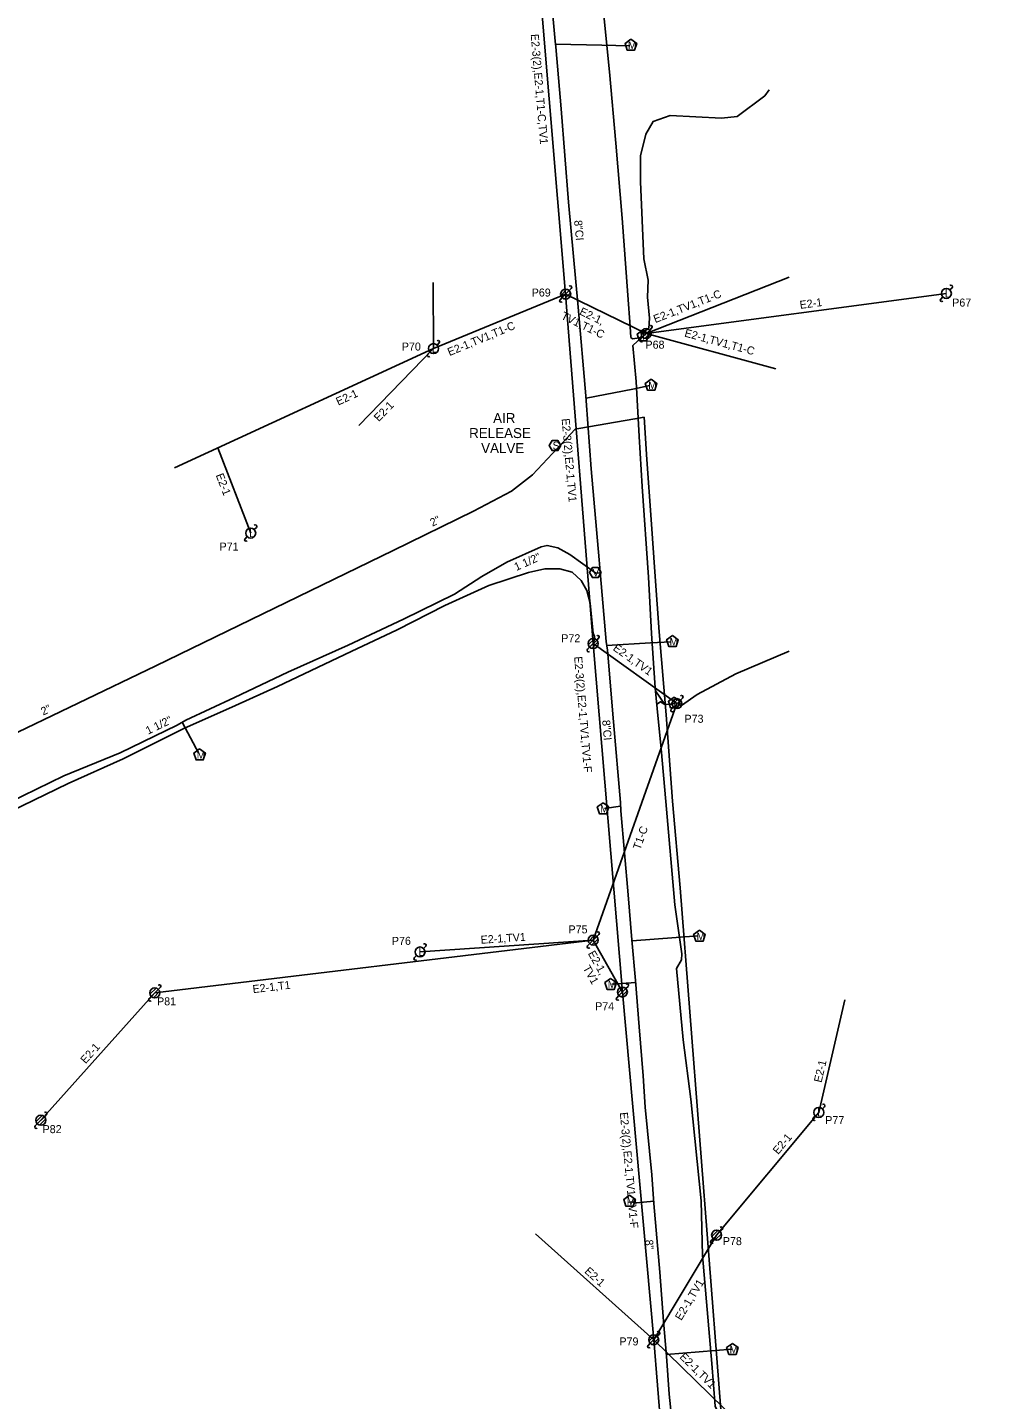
# Model space of a CAD drawing. Extents: x 1614474 to 1865144, y 1098877 to 1212550.
# Drawn here: x 1755985 to 1756469, y 1168201 to 1168887 of the extents above; entities that cross this region are included whole.
import ezdxf

# ---------------------------------------------------------------- set-up
doc = ezdxf.new("R2010")
doc.units = 0
for name, color, linetype in [('RD_EX_SU_Elec', 7, 'Continuous'), ('RD_EX_SU_H2O', 7, 'Continuous'), ('RD_EX_SU_Ovhd', 7, 'Continuous'), ('RD_EX_SU_Pole', 7, 'Continuous'), ('RD_EX_SU_Sewer', 7, 'Continuous'), ('RD_EX_SU_Telecom', 7, 'Continuous'), ('RD_EX_SU_TX_H2O', 7, 'Continuous'), ('RD_EX_SU_TX_Pole', 7, 'Continuous'), ('RD_EX_SU_TX_Sewer', 7, 'Continuous')]:
    doc.layers.add(name, color=color, linetype=linetype)

# ---------------------------------------------------------------- blocks, each defined once
blk = doc.blocks.new('SUE_PP')
at = {"layer": 'RD_EX_SU_Pole'}
for p, q in [((-2.41, -0.65), (0.65, 2.41)), ((-1.77, -1.77), (1.77, 1.77)), ((-0.65, -2.41), (2.41, 0.65)), ((1.77, 1.77), (2.83, 2.83)), ((-2.83, -2.83), (-1.77, -1.77))]:
    blk.add_line(p, q, dxfattribs=at)
blk.add_circle((0, 0), 2.5, dxfattribs=at)
for centre, start, end in [((2.3, 3.36), 315, 135), ((-2.3, -3.36), 135, 315)]:
    blk.add_arc(centre, 0.75, start, end, dxfattribs=at)
blk = doc.blocks.new('SUE_WM')
at = {"layer": 'RD_EX_SU_H2O'}
blk.add_lwpolyline([(0, 3.05), (-2.9, 0.94), (-1.79, -2.47), (1.79, -2.47), (2.9, 0.94)], close=True, dxfattribs=at)
blk.add_text('M', height=3.75, dxfattribs=at).set_placement((-1.43, -1.88))

msp = doc.modelspace()

# ---------------------------------------------------------------- linework, layer by layer
at = {"layer": 'RD_EX_SU_Elec'}
msp.add_lwpolyline([(1756310.9, 1168548.03), (1756311.85, 1168547.94), (1756319.53, 1168553.43), (1756338.93, 1168563.75), (1756365.66, 1168575.17)], dxfattribs=at)
at = {"layer": 'RD_EX_SU_H2O'}
for p, q in [((1756062.25, 1168539.6), (1756070.5, 1168524)), ((1756273.26, 1168496.58), (1756281.34, 1168497.65)), ((1756287.04, 1168430.3), (1756320.14, 1168432.8)), ((1756288.92, 1168409.56), (1756276.99, 1168408.7)), ((1756304.2, 1168223.57), (1756336.98, 1168226.24))]:
    msp.add_line(p, q, dxfattribs=at)
for points in [[(1756215.37, 1169057.62), (1756230.39, 1169005.87), (1756236.54, 1168978.79), (1756239.26, 1168962.91), (1756241.89, 1168945.6), (1756243.12, 1168936.58), (1756246.24, 1168905.88), (1756248.65, 1168879.97), (1756248.92, 1168877.19), (1756251.65, 1168846.26), (1756255.24, 1168799.63), (1756260.07, 1168747.12), (1756263.99, 1168702.78), (1756264.18, 1168700.31), (1756266.66, 1168666.35), (1756270.56, 1168620.84), (1756271.23, 1168612.87), (1756274.2, 1168580.03), (1756274.73, 1168575.57), (1756277.71, 1168539.82), (1756281.24, 1168499.51), (1756281.45, 1168495.4), (1756285.17, 1168453.36)], [(1756248.78, 1168878.57), (1756272.01, 1168878.03), (1756285.94, 1168877.77)], [(1756264.08, 1168701.54), (1756287.44, 1168706.15), (1756295.88, 1168707.93)], [(1755975.7, 1168499.57), (1756003.04, 1168512.76), (1756031.13, 1168524.34), (1756059.76, 1168538.21), (1756064.06, 1168540.6), (1756088.33, 1168551.96), (1756115.01, 1168564.64), (1756145.13, 1168578.2), (1756172.77, 1168591.2), (1756198.31, 1168603.56), (1756212.03, 1168612.5), (1756224.54, 1168619.67), (1756241.62, 1168627.3), (1756244.58, 1168627.99), (1756249.94, 1168626.83), (1756255.98, 1168623.41), (1756268.92, 1168614.21), (1756271.1, 1168614.34)], [(1756274.45, 1168577.9), (1756296.33, 1168579.27), (1756306.66, 1168579.86)], [(1756285.17, 1168453.36), (1756286.98, 1168430.89), (1756288.84, 1168410.54), (1756290.69, 1168387.38), (1756292.59, 1168362.89), (1756293.61, 1168347.16), (1756296.92, 1168313.47), (1756298.02, 1168299), (1756300.93, 1168264.73), (1756302.72, 1168240.2), (1756304.28, 1168222.7), (1756305.65, 1168203.75), (1756307.59, 1168184.55), (1756309.19, 1168163.34), (1756313.11, 1168117.87), (1756314.27, 1168105.58), (1756316.49, 1168082.9), (1756317.85, 1168067.08)], [(1756297.93, 1168300.23), (1756289.24, 1168299.38), (1756286.37, 1168299.96)]]:
    msp.add_lwpolyline(points, dxfattribs=at)
for points in [[(1756286.47, 1168881.05), (1756283.57, 1168878.94), (1756284.68, 1168875.53), (1756288.26, 1168875.53), (1756289.37, 1168878.94)], [(1756296.58, 1168711.11), (1756293.68, 1168709), (1756294.79, 1168705.59), (1756298.37, 1168705.59), (1756299.48, 1168709)], [(1756271.59, 1168614.42), (1756270.14, 1168616.92), (1756267.26, 1168616.92), (1756265.81, 1168614.42), (1756267.26, 1168611.92), (1756270.14, 1168611.92)], [(1756307.26, 1168582.93), (1756304.36, 1168580.82), (1756305.47, 1168577.41), (1756309.06, 1168577.41), (1756310.16, 1168580.82)], [(1756070.92, 1168526.31), (1756068.02, 1168524.2), (1756069.13, 1168520.79), (1756072.71, 1168520.79), (1756073.82, 1168524.2)], [(1756272.55, 1168499.41), (1756269.65, 1168497.3), (1756270.76, 1168493.89), (1756274.34, 1168493.89), (1756275.45, 1168497.3)]]:
    msp.add_lwpolyline(points, close=True, dxfattribs=at)
at = {"layer": 'RD_EX_SU_Ovhd'}
for p, q in [((1756241.59, 1168899.03), (1756253.88, 1168753.63)), ((1756294.1, 1168733.88), (1756365.67, 1168762.04)), ((1756187.81, 1168726.37), (1756187.57, 1168759.45)), ((1756294.1, 1168733.88), (1756444.18, 1168753.95)), ((1756187.81, 1168726.37), (1756253.88, 1168753.63)), ((1756253.88, 1168753.63), (1756294.1, 1168733.88)), ((1756253.88, 1168753.63), (1756267.62, 1168578.94)), ((1756294.1, 1168733.88), (1756358.94, 1168716.31)), ((1756058.29, 1168666.79), (1756187.81, 1168726.37)), ((1756150.48, 1168687.93), (1756187.81, 1168726.37)), ((1756080.07, 1168676.81), (1756096.45, 1168634.17)), ((1756267.62, 1168578.94), (1756309.52, 1168548.91)), ((1756267.62, 1168578.94), (1756282.23, 1168404.77)), ((1756267.68, 1168430.74), (1756309.52, 1168548.91)), ((1756048.5, 1168404.33), (1756267.68, 1168430.74)), ((1756181.09, 1168424.8), (1756267.68, 1168430.74)), ((1756267.68, 1168430.74), (1756282.23, 1168404.77)), ((1755991.54, 1168340.68), (1756048.5, 1168404.33)), ((1756282.23, 1168404.77), (1756297.87, 1168230.98)), ((1756380.41, 1168344.61), (1756393.49, 1168400.89)), ((1756329.33, 1168283.25), (1756380.41, 1168344.61)), ((1756238.72, 1168284), (1756297.87, 1168230.98)), ((1756297.87, 1168230.98), (1756329.33, 1168283.25)), ((1756297.87, 1168230.98), (1756339.88, 1168189.94)), ((1756297.87, 1168230.98), (1756312.84, 1168052.28))]:
    msp.add_line(p, q, dxfattribs=at)
at = {"layer": 'RD_EX_SU_Pole'}
for p, q in [((1756445.95, 1168755.71), (1756447.01, 1168756.78)), ((1756441.35, 1168751.12), (1756442.41, 1168752.18)), ((1756291.68, 1168733.24), (1756294.75, 1168736.3)), ((1756292.33, 1168732.12), (1756295.87, 1168735.65)), ((1756293.45, 1168731.47), (1756296.51, 1168734.53)), ((1756295.87, 1168735.65), (1756296.93, 1168736.71)), ((1756189.58, 1168728.14), (1756190.64, 1168729.2)), ((1756291.27, 1168731.05), (1756292.33, 1168732.12)), ((1756184.99, 1168723.54), (1756186.05, 1168724.6)), ((1756093.62, 1168631.34), (1756094.68, 1168632.4)), ((1756098.22, 1168635.93), (1756099.28, 1168636.99)), ((1756264.79, 1168576.11), (1756265.85, 1168577.17)), ((1756265.21, 1168578.29), (1756268.27, 1168581.35)), ((1756265.85, 1168577.17), (1756269.39, 1168580.71)), ((1756266.97, 1168576.52), (1756270.04, 1168579.59)), ((1756269.39, 1168580.71), (1756270.45, 1168581.77)), ((1756307.1, 1168548.26), (1756310.17, 1168551.32)), ((1756307.75, 1168547.14), (1756311.29, 1168550.67)), ((1756308.87, 1168546.49), (1756311.93, 1168549.55)), ((1756311.29, 1168550.67), (1756312.35, 1168551.73)), ((1756306.69, 1168546.08), (1756307.75, 1168547.14)), ((1756182.85, 1168426.57), (1756183.92, 1168427.63)), ((1756178.26, 1168421.98), (1756179.32, 1168423.04)), ((1756046.08, 1168403.69), (1756049.15, 1168406.75)), ((1756046.73, 1168402.57), (1756050.27, 1168406.1)), ((1756047.85, 1168401.92), (1756050.91, 1168404.98)), ((1756050.27, 1168406.1), (1756051.33, 1168407.16)), ((1756045.67, 1168401.51), (1756046.73, 1168402.57)), ((1755989.13, 1168340.03), (1755992.19, 1168343.1)), ((1755993.31, 1168342.45), (1755994.37, 1168343.51)), ((1756377.58, 1168341.79), (1756378.65, 1168342.85)), ((1756382.18, 1168346.38), (1756383.24, 1168347.44)), ((1755988.72, 1168337.85), (1755989.78, 1168338.91)), ((1755989.78, 1168338.91), (1755993.31, 1168342.45)), ((1755990.9, 1168338.27), (1755993.96, 1168341.33))]:
    msp.add_line(p, q, dxfattribs=at)
for centre in [(1756444.18, 1168753.95), (1756294.1, 1168733.88), (1756187.81, 1168726.37), (1756096.45, 1168634.17), (1756267.62, 1168578.94), (1756309.52, 1168548.91), (1756181.09, 1168424.8), (1756048.5, 1168404.33), (1755991.54, 1168340.68), (1756380.41, 1168344.61)]:
    msp.add_circle(centre, 2.5, dxfattribs=at)
for centre, start, end in [((1756446.48, 1168757.31), 315, 135), ((1756441.88, 1168750.59), 135, 315), ((1756296.4, 1168737.24), 315, 135), ((1756190.11, 1168729.73), 315, 135), ((1756291.8, 1168730.52), 135, 315), ((1756185.52, 1168723.01), 135, 315), ((1756098.75, 1168637.52), 315, 135), ((1756094.15, 1168630.81), 135, 315), ((1756269.92, 1168582.3), 315, 135), ((1756265.32, 1168575.58), 135, 315), ((1756311.82, 1168552.26), 315, 135), ((1756307.22, 1168545.55), 135, 315), ((1756183.39, 1168428.16), 315, 135), ((1756178.79, 1168421.45), 135, 315), ((1756050.8, 1168407.69), 315, 135), ((1756046.2, 1168400.98), 135, 315), ((1755993.84, 1168344.04), 315, 135), ((1756382.71, 1168347.97), 315, 135), ((1755989.25, 1168337.32), 135, 315), ((1756378.11, 1168341.26), 135, 315)]:
    msp.add_arc(centre, 0.75, start, end, dxfattribs=at)
at = {"layer": 'RD_EX_SU_Sewer'}
for points in [[(1755833.4, 1168520.19), (1755854.68, 1168510.84), (1755875.52, 1168502.34), (1755895.06, 1168493.1), (1755930.11, 1168510.09), (1755971.34, 1168530.46), (1756049.09, 1168567.75), (1756167.6, 1168625.42), (1756207.81, 1168645.15), (1756226.79, 1168655.14), (1756237.27, 1168663.29), (1756249.83, 1168676.69), (1756258.66, 1168686.07), (1756260.41, 1168686.42), (1756288.47, 1168691.24), (1756293.05, 1168692.1), (1756294.39, 1168670.91), (1756296.55, 1168641.01), (1756298.7, 1168612.4), (1756300.63, 1168584.8), (1756304.07, 1168543.33), (1756307.31, 1168500.11), (1756311.13, 1168456.78)], [(1756311.13, 1168456.78), (1756340.11, 1168085.05), (1756468.76, 1168092.7)]]:
    msp.add_lwpolyline(points, dxfattribs=at)
msp.add_lwpolyline([(1756251.47, 1168677.88), (1756250.02, 1168680.38), (1756247.13, 1168680.38), (1756245.69, 1168677.88), (1756247.13, 1168675.38), (1756250.02, 1168675.38)], close=True, dxfattribs=at)
at = {"layer": 'RD_EX_SU_Telecom'}
for p, q in [((1756293.19, 1168733.16), (1756293.87, 1168733.5)), ((1756298.77, 1168555.29), (1756303.45, 1168548.55)), ((1756303.45, 1168548.55), (1756307.13, 1168548.81)), ((1756308.14, 1168548.73), (1756308.41, 1168548.95))]:
    msp.add_line(p, q, dxfattribs=at)
for points in [[(1756174.94, 1169278.95), (1756160.29, 1169274.63), (1756159.03, 1169273.37), (1756165.27, 1169254.63), (1756173.7, 1169231.35), (1756183.01, 1169207.77), (1756193.5, 1169184.2), (1756200.36, 1169172.13), (1756213.48, 1169138.98), (1756222.54, 1169112.66), (1756230.85, 1169093.5), (1756238.34, 1169069.67), (1756245.15, 1169047.16), (1756251.74, 1169025.59), (1756258.67, 1168998.39), (1756265.3, 1168962.17), (1756268.66, 1168936.68), (1756271.99, 1168905.49), (1756273.23, 1168889.45), (1756275.78, 1168864.66), (1756278.96, 1168829.09), (1756282.05, 1168791.5), (1756284.91, 1168753.06), (1756286.16, 1168737.41)], [(1756292.67, 1168733.31), (1756293.39, 1168735.3), (1756295.52, 1168736.44), (1756295.74, 1168741.6), (1756294.85, 1168752.15), (1756295.1, 1168760.59), (1756292.91, 1168771.17), (1756291.26, 1168809.66), (1756291.35, 1168822.77), (1756293.92, 1168833.48), (1756297.58, 1168839.9), (1756306.15, 1168842.88), (1756331.85, 1168841.48), (1756339.56, 1168842.45), (1756353.44, 1168852.75), (1756355.66, 1168855.7)], [(1756286.16, 1168737.41), (1756286.44, 1168731.95), (1756287.27, 1168731.22), (1756290.84, 1168731.69), (1756292.18, 1168732.6)], [(1756292.28, 1168732.37), (1756287.5, 1168727.91), (1756289.04, 1168709.92), (1756290.67, 1168682.41), (1756292.1, 1168657.37), (1756295.3, 1168612.12), (1756296.82, 1168584.05), (1756298.63, 1168556.78), (1756299.56, 1168546.57), (1756301.65, 1168526.28), (1756303.91, 1168500.06), (1756308.42, 1168448.32)], [(1755964.85, 1168489.47), (1756005.15, 1168509.07), (1756032.74, 1168521.32), (1756062.96, 1168536.44), (1756088.88, 1168547.91), (1756109.77, 1168557.41), (1756146.73, 1168574.9), (1756169.62, 1168585.89), (1756193.45, 1168598.04), (1756215.54, 1168607.94), (1756235.28, 1168614.53), (1756243.52, 1168616.32), (1756250.98, 1168616.31), (1756257.16, 1168614.56), (1756261.69, 1168610.41), (1756264.47, 1168605.48), (1756266.13, 1168599.1), (1756267.65, 1168584.1), (1756268.31, 1168582.49), (1756268.17, 1168580.06)], [(1756307.4, 1168548.66), (1756303.49, 1168548.53), (1756301.24, 1168549.84), (1756299.37, 1168548.62)], [(1756308.42, 1168448.32), (1756311.91, 1168423.81), (1756311.76, 1168420.79), (1756309.33, 1168416.48), (1756312.58, 1168380.89), (1756316.49, 1168351.19), (1756321.57, 1168300.36), (1756322.32, 1168273.16), (1756326.95, 1168219.13), (1756328.55, 1168197.8), (1756329.78, 1168195.34), (1756338.22, 1168190.16)]]:
    msp.add_lwpolyline(points, dxfattribs=at)
for points in [[(1756292.52, 1168735.74), (1756289.66, 1168733.67), (1756290.75, 1168730.31), (1756294.28, 1168730.31), (1756295.37, 1168733.67)], [(1756308.09, 1168552.21), (1756305.23, 1168550.14), (1756306.32, 1168546.79), (1756309.85, 1168546.79), (1756310.94, 1168550.14)]]:
    msp.add_lwpolyline(points, close=True, dxfattribs=at)

# ---------------------------------------------------------------- block references
at = {"layer": 'RD_EX_SU_H2O'}
for p in [(1756320.75, 1168432.64), (1756276.37, 1168408.55), (1756285.82, 1168300.15), (1756337.24, 1168226.1)]:
    msp.add_blockref('SUE_WM', p, dxfattribs=at)
at = {"layer": 'RD_EX_SU_Pole'}
for p in [(1756253.88, 1168753.63), (1756267.68, 1168430.74), (1756282.23, 1168404.77), (1756329.33, 1168283.25), (1756297.87, 1168230.98)]:
    msp.add_blockref('SUE_PP', p, dxfattribs=at)

# ---------------------------------------------------------------- texts
at = {"layer": 'RD_EX_SU_H2O'}
for s, p in [('M', (1756285.04, 1168876.12)), ('M', (1756295.15, 1168706.18)), ('V', (1756267.27, 1168612.54)), ('M', (1756305.83, 1168578)), ('M', (1756069.49, 1168521.38)), ('M', (1756271.12, 1168494.48))]:
    msp.add_text(s, height=3.75, dxfattribs=at).set_placement(p)
at = {"layer": 'RD_EX_SU_Ovhd'}
for s, rotation, p in [('E2-3(2),E2-1,T1-C,TV1', 274.8814, (1756236.41, 1168883.46)), ('E2-1,TV1,T1-C', 21.4774, (1756298.69, 1168739.09)), ('E2-1', 7.61467, (1756371.13, 1168746.2)), ('TV1,T1-C', 334.04498, (1756251.22, 1168741.41)), ('E2-1,', 334.04498, (1756260.42, 1168743.6)), ('E2-1,TV1,T1-C', 22.53643, (1756195.81, 1168722.6)), ('E2-1,TV1,T1-C', 344.84084, (1756312.98, 1168732.46)), ('E2-1', 24.70154, (1756140.19, 1168697.86)), ('E2-1', 45.83763, (1756160.45, 1168689.58)), ('E2-3(2),E2-1,TV1', 274.8814, (1756251.87, 1168691.31)), ('E2-1', 291.01381, (1756078.9, 1168663.12)), ('E2-1,TV1', 324.36679, (1756277.19, 1168575.91)), ('E2-3(2),E2-1,TV1,TV1-F', 274.8814, (1756258.1, 1168572.35)), ('T1-C', 70.62036, (1756291.16, 1168475.58)), ('E2-1,TV1', 3.90186, (1756211.52, 1168428.88)), ('E2-1,', 299.21944, (1756264.87, 1168424.05)), ('TV1', 299.21944, (1756262.34, 1168416.76)), ('E2-1,T1', 6.85827, (1756097.64, 1168404.2)), ('E2-1', 48.17839, (1756013.89, 1168368.65)), ('E2-1', 76.91882, (1756381.76, 1168359.27)), ('E2-3(2),E2-1,TV1,TV1-F', 275.24837, (1756280.94, 1168344.53)), ('E2-1', 50.22086, (1756360.08, 1168323.31)), ('E2-1', 317.57367, (1756263, 1168264.78)), ('E2-1,TV1', 59.1195, (1756311.68, 1168240.3)), ('E2-1,TV1', 315.44772, (1756310.53, 1168222.04))]:
    msp.add_text(s, height=4, rotation=rotation, dxfattribs=at).set_placement(p)
at = {"layer": 'RD_EX_SU_Pole'}
for p in [(1756443.32, 1168751.95), (1756186.95, 1168724.37), (1756095.59, 1168632.17), (1756180.22, 1168422.8), (1756379.55, 1168342.61)]:
    msp.add_text('L', height=4, dxfattribs=at).set_placement(p)
at = {"layer": 'RD_EX_SU_Sewer'}
msp.add_text('S', height=4, dxfattribs=at).set_placement((1756247.35, 1168675.88))
at = {"layer": 'RD_EX_SU_Telecom'}
for p in [(1756291.26, 1168730.86), (1756306.83, 1168547.34)]:
    msp.add_text('T', height=3.75, dxfattribs=at).set_placement(p)
at = {"layer": 'RD_EX_SU_TX_H2O'}
for s, rotation, p in [('8"CI', 275.25838, (1756258.09, 1168790.39)), ('1 1/2"', 24.06543, (1756229.23, 1168615.19)), ('1 1/2"', 25.84632, (1756045.15, 1168533.36)), ('8"CI', 275.00476, (1756272.1, 1168540.58)), ('8"', 274.85063, (1756293.54, 1168280.84))]:
    msp.add_text(s, height=4, rotation=rotation, dxfattribs=at).set_placement(p)
at = {"layer": 'RD_EX_SU_TX_Pole'}
for s, p in [('P69', (1756236.9, 1168752.4)), ('P67', (1756447.09, 1168747.38)), ('P70', (1756171.97, 1168725.4)), ('P68', (1756293.77, 1168726.34)), ('P71', (1756080.87, 1168625.42)), ('P72', (1756251.68, 1168579.6)), ('P73', (1756313.27, 1168539.36)), ('P76', (1756167, 1168428.36)), ('P75', (1756255.29, 1168434.09)), ('P81', (1756049.63, 1168398.13)), ('P74', (1756268.6, 1168395.68)), ('P77', (1756383.64, 1168338.75)), ('P82', (1755992.41, 1168334.24)), ('P78', (1756332.44, 1168278.27)), ('P79', (1756280.74, 1168228.14))]:
    msp.add_text(s, height=4, dxfattribs=at).set_placement(p)
at = {"layer": 'RD_EX_SU_TX_Sewer'}
for s, p in [('AIR', (1756217.62, 1168689.16)), ('RELEASE ', (1756205.63, 1168681.66)), ('VALVE', (1756211.63, 1168674.16))]:
    msp.add_text(s, height=5, dxfattribs=at).set_placement(p)
for rotation, p in [(26.14216, (1756187.28, 1168637.3)), (25.62051, (1755992.73, 1168542.94))]:
    msp.add_text('2"', height=4, rotation=rotation, dxfattribs=at).set_placement(p)

doc.saveas('drawing.dxf')
